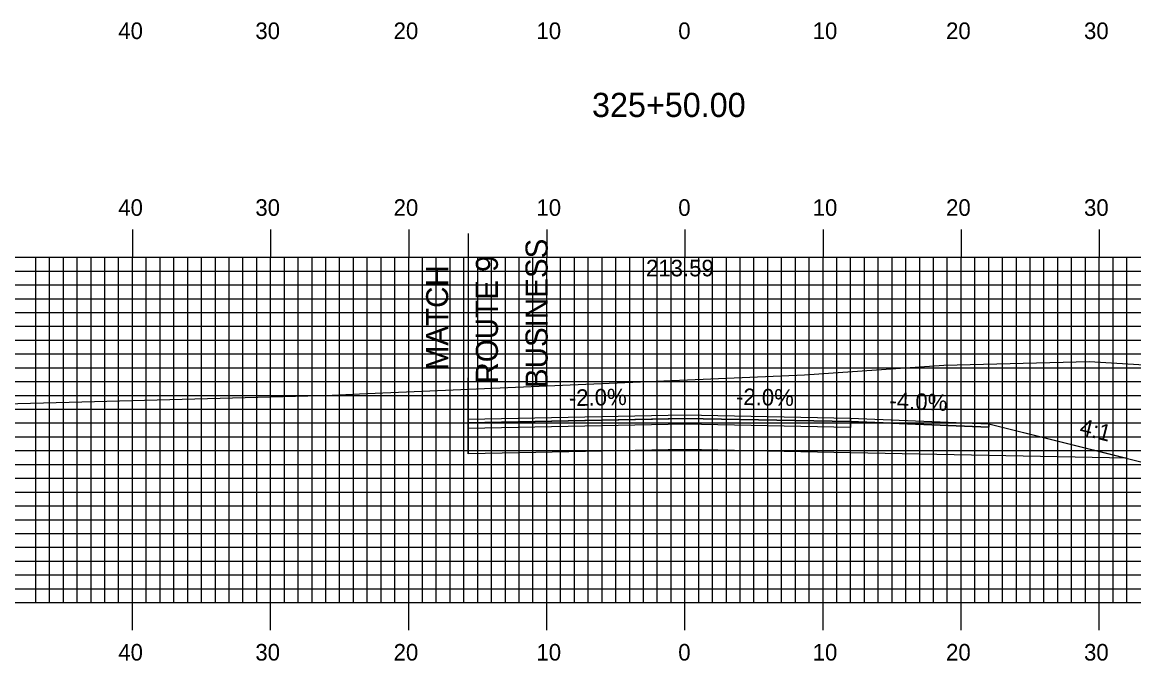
# Model space of a CAD drawing. Extents: x 1821211 to 1821555, y 442591 to 442811.
# Drawn here: x 1821329.2 to 1821409.7, y 442644.4 to 442690.7 of the extents above; entities that cross this region are included whole.
import ezdxf

# ---------------------------------------------------------------- set-up
doc = ezdxf.new("R2010")
doc.units = 0
for name, color, linetype in [('ANNOTATION', 7, 'Continuous'), ('D_Roadway_Centerline', 7, 'Continuous'), ('D_Roadway_Centerline_Text', 7, 'Continuous'), ('D_Roadway_Edge_Shoulder', 7, 'Continuous'), ('D_Roadway_Edge_TW', 7, 'Continuous'), ('D_Roadway_Pavement', 7, 'Continuous'), ('D_Roadway_SlopeLines', 7, 'Continuous'), ('D_Roadway_SubGrade', 7, 'Continuous'), ('H_V ANNOTATION', 7, 'Continuous'), ('MAJOR', 7, 'Continuous'), ('MINOR', 7, 'Continuous'), ('S_Roadway_Centerline', 7, 'Continuous')]:
    doc.layers.add(name, color=color, linetype=linetype)

msp = doc.modelspace()

# ---------------------------------------------------------------- linework, layer by layer
at = {"layer": 'ANNOTATION'}
msp.add_line((1821361.53, 442659.438), (1821361.53, 442664.933), dxfattribs=at)
at = {"layer": 'D_Roadway_Edge_Shoulder'}
msp.add_lwpolyline([(1821389.23, 442662.012), (1821399.23, 442661.612), (1821399.23, 442661.362), (1821389.23, 442661.762)], close=True, dxfattribs=at)
at = {"layer": 'D_Roadway_Edge_TW'}
msp.add_lwpolyline([(1821361.53, 442661.665), (1821361.53, 442661.938), (1821377.23, 442662.252), (1821389.23, 442662.012), (1821389.23, 442661.762), (1821377.23, 442662.002)], close=True, dxfattribs=at)
at = {"layer": 'D_Roadway_Pavement'}
msp.add_lwpolyline([(1821361.53, 442661.271), (1821361.53, 442661.665), (1821377.295, 442661.981), (1821389.23, 442661.762), (1821389.23, 442661.345), (1821377.23, 442661.585)], close=True, dxfattribs=at)
at = {"layer": 'D_Roadway_SlopeLines'}
msp.add_lwpolyline([(1821399.23, 442661.612), (1821413.23, 442658.112)], dxfattribs=at)
at = {"layer": 'D_Roadway_SubGrade'}
msp.add_line((1821361.53, 442675.389), (1821361.53, 442659.438), dxfattribs=at)
msp.add_lwpolyline([(1821365.23, 442659.512), (1821361.53, 442659.438), (1821361.53, 442661.271), (1821361.53, 442661.271), (1821361.53, 442661.665), (1821377.23, 442662.002), (1821389.23, 442661.762), (1821399.23, 442661.362), (1821399.23, 442661.612), (1821409.23, 442659.112), (1821389.23, 442659.512), (1821377.23, 442659.752)], close=True, dxfattribs=at)
at = {"layer": 'MAJOR'}
for p, q in [((1821337.23, 442675.669), (1821337.23, 442673.665)), ((1821347.23, 442675.669), (1821347.23, 442673.665)), ((1821357.23, 442675.669), (1821357.23, 442673.665)), ((1821367.23, 442675.669), (1821367.23, 442673.665)), ((1821377.23, 442675.669), (1821377.23, 442673.665)), ((1821387.23, 442675.669), (1821387.23, 442673.665)), ((1821397.23, 442675.669), (1821397.23, 442673.665)), ((1821407.23, 442675.669), (1821407.23, 442673.665)), ((1821237.23, 442673.665), (1821517.23, 442673.665)), ((1821237.23, 442673.665), (1821517.23, 442673.665)), ((1821337.23, 442648.665), (1821337.23, 442673.665)), ((1821347.23, 442648.665), (1821347.23, 442673.665)), ((1821357.23, 442648.665), (1821357.23, 442673.665)), ((1821367.23, 442648.665), (1821367.23, 442673.665)), ((1821377.23, 442648.665), (1821377.23, 442673.665)), ((1821387.23, 442648.665), (1821387.23, 442673.665)), ((1821397.23, 442648.665), (1821397.23, 442673.665)), ((1821407.23, 442648.665), (1821407.23, 442673.665)), ((1821237.23, 442668.665), (1821517.23, 442668.665)), ((1821237.23, 442663.665), (1821517.23, 442663.665)), ((1821237.23, 442658.665), (1821517.23, 442658.665)), ((1821237.23, 442653.665), (1821517.23, 442653.665)), ((1821237.23, 442648.665), (1821517.23, 442648.665)), ((1821237.23, 442648.665), (1821517.23, 442648.665)), ((1821337.23, 442646.661), (1821337.23, 442648.665)), ((1821347.23, 442646.661), (1821347.23, 442648.665)), ((1821357.23, 442646.661), (1821357.23, 442648.665)), ((1821367.23, 442646.661), (1821367.23, 442648.665)), ((1821377.23, 442646.661), (1821377.23, 442648.665)), ((1821387.23, 442646.661), (1821387.23, 442648.665)), ((1821397.23, 442646.661), (1821397.23, 442648.665)), ((1821407.23, 442646.661), (1821407.23, 442648.665))]:
    msp.add_line(p, q, dxfattribs=at)
at = {"layer": 'MINOR'}
for p, q in [((1821330.23, 442648.665), (1821330.23, 442673.665)), ((1821331.23, 442648.665), (1821331.23, 442673.665)), ((1821332.23, 442648.665), (1821332.23, 442673.665)), ((1821333.23, 442648.665), (1821333.23, 442673.665)), ((1821334.23, 442648.665), (1821334.23, 442673.665)), ((1821335.23, 442648.665), (1821335.23, 442673.665)), ((1821336.23, 442648.665), (1821336.23, 442673.665)), ((1821338.23, 442648.665), (1821338.23, 442673.665)), ((1821339.23, 442648.665), (1821339.23, 442673.665)), ((1821340.23, 442648.665), (1821340.23, 442673.665)), ((1821341.23, 442648.665), (1821341.23, 442673.665)), ((1821342.23, 442648.665), (1821342.23, 442673.665)), ((1821343.23, 442648.665), (1821343.23, 442673.665)), ((1821344.23, 442648.665), (1821344.23, 442673.665)), ((1821345.23, 442648.665), (1821345.23, 442673.665)), ((1821346.23, 442648.665), (1821346.23, 442673.665)), ((1821348.23, 442648.665), (1821348.23, 442673.665)), ((1821349.23, 442648.665), (1821349.23, 442673.665)), ((1821350.23, 442648.665), (1821350.23, 442673.665)), ((1821351.23, 442648.665), (1821351.23, 442673.665)), ((1821352.23, 442648.665), (1821352.23, 442673.665)), ((1821353.23, 442648.665), (1821353.23, 442673.665)), ((1821354.23, 442648.665), (1821354.23, 442673.665)), ((1821355.23, 442648.665), (1821355.23, 442673.665)), ((1821356.23, 442648.665), (1821356.23, 442673.665)), ((1821358.23, 442648.665), (1821358.23, 442673.665)), ((1821359.23, 442648.665), (1821359.23, 442673.665)), ((1821360.23, 442648.665), (1821360.23, 442673.665)), ((1821361.23, 442648.665), (1821361.23, 442673.665)), ((1821362.23, 442648.665), (1821362.23, 442673.665)), ((1821363.23, 442648.665), (1821363.23, 442673.665)), ((1821364.23, 442648.665), (1821364.23, 442673.665)), ((1821365.23, 442648.665), (1821365.23, 442673.665)), ((1821366.23, 442648.665), (1821366.23, 442673.665)), ((1821368.23, 442648.665), (1821368.23, 442673.665)), ((1821369.23, 442648.665), (1821369.23, 442673.665)), ((1821370.23, 442648.665), (1821370.23, 442673.665)), ((1821371.23, 442648.665), (1821371.23, 442673.665)), ((1821372.23, 442648.665), (1821372.23, 442673.665)), ((1821373.23, 442648.665), (1821373.23, 442673.665)), ((1821374.23, 442648.665), (1821374.23, 442673.665)), ((1821375.23, 442648.665), (1821375.23, 442673.665)), ((1821376.23, 442648.665), (1821376.23, 442673.665)), ((1821378.23, 442648.665), (1821378.23, 442673.665)), ((1821379.23, 442648.665), (1821379.23, 442673.665)), ((1821380.23, 442648.665), (1821380.23, 442673.665)), ((1821381.23, 442648.665), (1821381.23, 442673.665)), ((1821382.23, 442648.665), (1821382.23, 442673.665)), ((1821383.23, 442648.665), (1821383.23, 442673.665)), ((1821384.23, 442648.665), (1821384.23, 442673.665)), ((1821385.23, 442648.665), (1821385.23, 442673.665)), ((1821386.23, 442648.665), (1821386.23, 442673.665)), ((1821388.23, 442648.665), (1821388.23, 442673.665)), ((1821389.23, 442648.665), (1821389.23, 442673.665)), ((1821390.23, 442648.665), (1821390.23, 442673.665)), ((1821391.23, 442648.665), (1821391.23, 442673.665)), ((1821392.23, 442648.665), (1821392.23, 442673.665)), ((1821393.23, 442648.665), (1821393.23, 442673.665)), ((1821394.23, 442648.665), (1821394.23, 442673.665)), ((1821395.23, 442648.665), (1821395.23, 442673.665)), ((1821396.23, 442648.665), (1821396.23, 442673.665)), ((1821398.23, 442648.665), (1821398.23, 442673.665)), ((1821399.23, 442648.665), (1821399.23, 442673.665)), ((1821400.23, 442648.665), (1821400.23, 442673.665)), ((1821401.23, 442648.665), (1821401.23, 442673.665)), ((1821402.23, 442648.665), (1821402.23, 442673.665)), ((1821403.23, 442648.665), (1821403.23, 442673.665)), ((1821404.23, 442648.665), (1821404.23, 442673.665)), ((1821405.23, 442648.665), (1821405.23, 442673.665)), ((1821406.23, 442648.665), (1821406.23, 442673.665)), ((1821408.23, 442648.665), (1821408.23, 442673.665)), ((1821409.23, 442648.665), (1821409.23, 442673.665)), ((1821237.23, 442672.665), (1821517.23, 442672.665)), ((1821237.23, 442671.665), (1821517.23, 442671.665)), ((1821237.23, 442670.665), (1821517.23, 442670.665)), ((1821237.23, 442669.665), (1821517.23, 442669.665)), ((1821237.23, 442667.665), (1821517.23, 442667.665)), ((1821237.23, 442666.665), (1821517.23, 442666.665)), ((1821237.23, 442665.665), (1821517.23, 442665.665)), ((1821237.23, 442664.665), (1821517.23, 442664.665)), ((1821237.23, 442662.665), (1821517.23, 442662.665)), ((1821237.23, 442661.665), (1821517.23, 442661.665)), ((1821237.23, 442660.665), (1821517.23, 442660.665)), ((1821237.23, 442659.665), (1821517.23, 442659.665)), ((1821237.23, 442657.665), (1821517.23, 442657.665)), ((1821237.23, 442656.665), (1821517.23, 442656.665)), ((1821237.23, 442655.665), (1821517.23, 442655.665)), ((1821237.23, 442654.665), (1821517.23, 442654.665)), ((1821237.23, 442652.665), (1821517.23, 442652.665)), ((1821237.23, 442651.665), (1821517.23, 442651.665)), ((1821237.23, 442650.665), (1821517.23, 442650.665)), ((1821237.23, 442649.665), (1821517.23, 442649.665))]:
    msp.add_line(p, q, dxfattribs=at)
at = {"layer": 'S_Roadway_Centerline'}
msp.add_lwpolyline([(1821319.61, 442662.843), (1821333.555, 442663.186), (1821350.848, 442663.656), (1821351.687, 442663.677), (1821353.673, 442663.779), (1821385.884, 442665.142), (1821395.978, 442665.857), (1821406.516, 442666.122), (1821418.041, 442665.425), (1821418.632, 442665.434), (1821435.847, 442665.716), (1821444.877, 442665.86), (1821452.437, 442666.038), (1821463.838, 442666.014), (1821469.257, 442666.153), (1821479.158, 442666.306), (1821486.685, 442666.436), (1821500.062, 442666.402), (1821503.319, 442666.343), (1821509.481, 442666.371), (1821517.23, 442666.371)], dxfattribs=at)

# ---------------------------------------------------------------- texts
at = {"layer": 'ANNOTATION'}
for s, height, rotation, p in [('BUSINESS', 1.6, 90, (1821367.291, 442664.19)), ('ROUTE 9', 1.6, 90, (1821363.691, 442664.518)), ('MATCH', 1.6, 90, (1821360.091, 442665.48)), ('-2.0%', 1.2, 1.14576, (1821368.836, 442662.884)), ('-2.0%', 1.2, 358.85424, (1821380.916, 442662.978)), ('-4.0%', 1.2, 357.70939, (1821392.022, 442662.702)), ('4:1', 1.2, 345.96376, (1821405.736, 442660.847))]:
    msp.add_text(s, height=height, rotation=rotation, dxfattribs=at).set_placement(p)
at = {"layer": 'D_Roadway_Centerline'}
for s, p in [('C', (1821377.225, 442662.252)), ('L', (1821377.23, 442662.244))]:
    msp.add_text(s, height=0.0146, dxfattribs=at).set_placement(p)
at = {"layer": 'D_Roadway_Centerline_Text'}
msp.add_text('213.59', height=1.2, dxfattribs=at).set_placement((1821374.415, 442672.282))
at = {"layer": 'H_V ANNOTATION'}
for s, height, p in [('40', 1.2, (1821336.202, 442689.465)), ('30', 1.2, (1821346.127, 442689.465)), ('20', 1.2, (1821356.138, 442689.465)), ('10', 1.2, (1821366.481, 442689.465)), ('0', 1.2, (1821376.748, 442689.465)), ('10', 1.2, (1821386.481, 442689.465)), ('20', 1.2, (1821396.138, 442689.465)), ('30', 1.2, (1821406.127, 442689.465)), ('325+50.00', 1.75, (1821370.503, 442683.821)), ('40', 1.2, (1821336.202, 442676.665)), ('30', 1.2, (1821346.127, 442676.665)), ('20', 1.2, (1821356.138, 442676.665)), ('10', 1.2, (1821366.481, 442676.665)), ('0', 1.2, (1821376.748, 442676.665)), ('10', 1.2, (1821386.481, 442676.665)), ('20', 1.2, (1821396.138, 442676.665)), ('30', 1.2, (1821406.127, 442676.665)), ('40', 1.2, (1821336.202, 442644.465)), ('30', 1.2, (1821346.127, 442644.465)), ('20', 1.2, (1821356.138, 442644.465)), ('10', 1.2, (1821366.481, 442644.465)), ('0', 1.2, (1821376.748, 442644.465)), ('10', 1.2, (1821386.481, 442644.465)), ('20', 1.2, (1821396.138, 442644.465)), ('30', 1.2, (1821406.127, 442644.465))]:
    msp.add_text(s, height=height, dxfattribs=at).set_placement(p)

doc.saveas('drawing.dxf')
